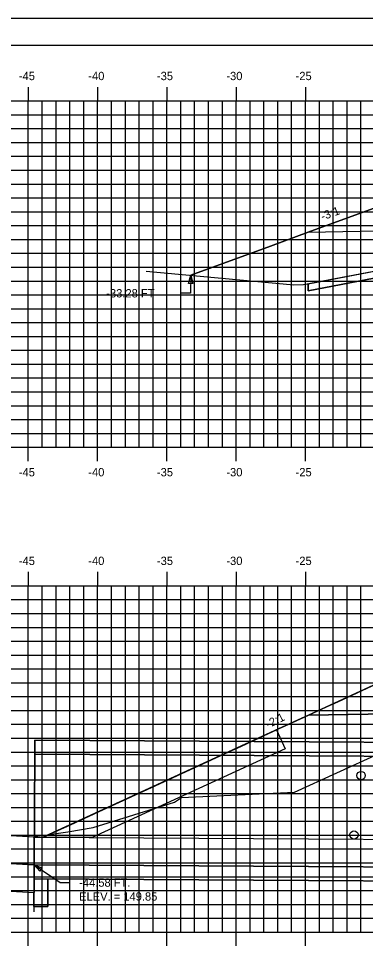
# Model space of a CAD drawing. Extents: x 1141202 to 1141372, y 608981 to 609091.
# Drawn here: x 1141239.8 to 1141264.8, y 609024.1 to 609091.3 of the extents above; entities that cross this region are included whole.
import ezdxf

# ---------------------------------------------------------------- set-up
doc = ezdxf.new("R2010")
doc.units = 0
for name, color, linetype in [('ANNOTATION', 7, 'Continuous'), ('BORDER', 7, 'Continuous'), ('D_Drainage_Culvert', 7, 'Continuous'), ('D_Roadway_SlopeLines', 7, 'Continuous'), ('D_Roadway_SubGrade', 7, 'Continuous'), ('D_Text_Standard', 7, 'Continuous'), ('H_V ANNOTATION', 7, 'Continuous'), ('JUNK', 7, 'Continuous'), ('MAJOR', 7, 'Continuous'), ('MINOR', 7, 'Continuous'), ('PATTERNING', 7, 'Continuous'), ('PLOT BOUNDARY', 7, 'Continuous'), ('S_Drainage_Invert', 7, 'Continuous'), ('S_Roadway_Centerline', 7, 'Continuous'), ('SHADING', 7, 'Continuous')]:
    doc.layers.add(name, color=color, linetype=linetype)

msp = doc.modelspace()

# ---------------------------------------------------------------- linework, layer by layer
for points in [[(1141252.234, 609072.746), (1141257.978, 609074.853), (1141260.705, 609075.853), (1141267.513, 609078.349), (1141267.514, 609078.349), (1141274.514, 609078.629), (1141285.514, 609078.849), (1141296.514, 609078.629), (1141303.514, 609078.349), (1141309.224, 609075.875), (1141311.532, 609074.875), (1141326.721, 609068.292)], [(1141242.002, 609032.375), (1141243.124, 609032.891), (1141243.238, 609032.944), (1141245.256, 609033.872), (1141245.575, 609034.019), (1141247.445, 609034.879), (1141247.911, 609035.094), (1141249.603, 609035.873), (1141250.246, 609036.168), (1141251.729, 609036.851), (1141252.581, 609037.243), (1141252.713, 609037.304), (1141252.823, 609037.354), (1141253.764, 609037.788), (1141254.915, 609038.318), (1141255.575, 609038.621), (1141257.249, 609039.392), (1141257.489, 609039.502), (1141258.565, 609039.998), (1141259.055, 609040.223), (1141259.583, 609040.466), (1141260.728, 609040.994), (1141261.554, 609041.374), (1141261.916, 609041.54), (1141262.843, 609041.967), (1141264.248, 609042.614), (1141266.045, 609043.442)]]:
    msp.add_lwpolyline(points)
at = {"layer": 'BORDER'}
msp.add_lwpolyline([(1141210.514, 608984.335), (1141370.514, 608984.335), (1141370.514, 609089.335), (1141210.514, 609089.335)], close=True, dxfattribs=at)
at = {"layer": 'D_Drainage_Culvert'}
for points in [[(1141240.936, 609030.185), (1141240.985, 609038.185), (1141240.991, 609039.185), (1141335.989, 609038.605), (1141335.983, 609037.605), (1141335.934, 609029.606), (1141335.916, 609026.606), (1141334.916, 609026.612), (1141334.928, 609028.612), (1141335.928, 609028.606), (1141240.93, 609029.185), (1141240.918, 609027.185), (1141241.918, 609027.179), (1141241.93, 609029.179)], [(1141240.934, 609030.185), (1141335.934, 609029.606), (1141335.983, 609037.605), (1141240.985, 609038.185), (1141240.936, 609030.185)]]:
    msp.add_lwpolyline(points, dxfattribs=at)
at = {"layer": 'D_Roadway_SlopeLines'}
for p, q in [((1141260.705, 609072.14), (1141260.705, 609071.631)), ((1141260.721, 609040.991), (1141241.588, 609032.181))]:
    msp.add_line(p, q, dxfattribs=at)
for points in [[(1141260.705, 609075.853), (1141257.978, 609074.853)], [(1141257.978, 609074.853), (1141252.234, 609072.746)], [(1141260.705, 609071.631), (1141269.611, 609073.326), (1141272.09, 609073.949), (1141272.463, 609073.997), (1141275.785, 609074.489)], [(1141260.728, 609040.994), (1141258.565, 609039.998)], [(1141258.565, 609039.998), (1141242.002, 609032.375)]]:
    msp.add_lwpolyline(points, dxfattribs=at)
msp.add_lwpolyline([(1141273.617, 609041.209), (1141260.721, 609040.991), (1141266.047, 609043.443), (1141266.047, 609043.193), (1141273.617, 609043.459)], close=True, dxfattribs=at)
at = {"layer": 'D_Roadway_SubGrade'}
for points in [[(1141274.514, 609078.212), (1141274.514, 609078.379), (1141267.514, 609078.099), (1141267.514, 609078.349), (1141267.513, 609078.349), (1141260.705, 609075.853), (1141274.514, 609076.129)], [(1141273.617, 609043.291), (1141273.617, 609043.458), (1141266.046, 609043.192), (1141266.046, 609043.442), (1141266.045, 609043.442), (1141260.728, 609040.994), (1141273.617, 609041.208)]]:
    msp.add_lwpolyline(points, close=True, dxfattribs=at)
at = {"layer": 'D_Text_Standard'}
for points in [[(1141252.234, 609072.746), (1141252.22, 609071.45), (1141251.54, 609071.45)], [(1141240.934, 609030.185), (1141242.82, 609028.91), (1141243.5, 609028.91)]]:
    msp.add_lwpolyline(points, dxfattribs=at)
for points in [[(1141252.234, 609072.746), (1141252.373, 609072.163), (1141252.082, 609072.166)], [(1141240.934, 609030.185), (1141241.498, 609029.98), (1141241.335, 609029.739)]]:
    msp.add_lwpolyline(points, close=True, dxfattribs=at)
at = {"layer": 'JUNK'}
msp.add_lwpolyline([(1141240.97, 609036.102), (1141240.934, 609030.185), (1141240.913, 609026.794)], dxfattribs=at)
at = {"layer": 'MAJOR'}
for p, q in [((1141240.514, 609086.337), (1141240.514, 609085.335)), ((1141245.514, 609086.337), (1141245.514, 609085.335)), ((1141250.514, 609086.337), (1141250.514, 609085.335)), ((1141255.514, 609086.337), (1141255.514, 609085.335)), ((1141260.514, 609086.337), (1141260.514, 609085.335)), ((1141215.514, 609085.335), (1141355.514, 609085.335)), ((1141215.514, 609085.335), (1141355.514, 609085.335)), ((1141240.514, 609060.335), (1141240.514, 609085.335)), ((1141245.514, 609060.335), (1141245.514, 609085.335)), ((1141250.514, 609060.335), (1141250.514, 609085.335)), ((1141255.514, 609060.335), (1141255.514, 609085.335)), ((1141260.514, 609060.335), (1141260.514, 609085.335)), ((1141215.514, 609080.335), (1141355.514, 609080.335)), ((1141215.514, 609075.335), (1141355.514, 609075.335)), ((1141215.514, 609070.335), (1141355.514, 609070.335)), ((1141215.514, 609065.335), (1141355.514, 609065.335)), ((1141215.514, 609060.335), (1141355.514, 609060.335)), ((1141215.514, 609060.335), (1141355.514, 609060.335)), ((1141240.514, 609059.333), (1141240.514, 609060.335)), ((1141245.514, 609059.333), (1141245.514, 609060.335)), ((1141250.514, 609059.333), (1141250.514, 609060.335)), ((1141255.514, 609059.333), (1141255.514, 609060.335)), ((1141260.514, 609059.333), (1141260.514, 609060.335)), ((1141240.514, 609051.337), (1141240.514, 609050.335)), ((1141245.514, 609051.337), (1141245.514, 609050.335)), ((1141250.514, 609051.337), (1141250.514, 609050.335)), ((1141255.514, 609051.337), (1141255.514, 609050.335)), ((1141260.514, 609051.337), (1141260.514, 609050.335)), ((1141215.514, 609050.335), (1141355.514, 609050.335)), ((1141215.514, 609050.335), (1141355.514, 609050.335)), ((1141240.514, 609025.335), (1141240.514, 609050.335)), ((1141245.514, 609025.335), (1141245.514, 609050.335)), ((1141250.514, 609025.335), (1141250.514, 609050.335)), ((1141255.514, 609025.335), (1141255.514, 609050.335)), ((1141260.514, 609025.335), (1141260.514, 609050.335)), ((1141215.514, 609045.335), (1141355.514, 609045.335)), ((1141215.514, 609040.335), (1141355.514, 609040.335)), ((1141215.514, 609035.335), (1141355.514, 609035.335)), ((1141215.514, 609030.335), (1141355.514, 609030.335)), ((1141215.514, 609025.335), (1141355.514, 609025.335)), ((1141215.514, 609025.335), (1141355.514, 609025.335)), ((1141240.514, 609024.333), (1141240.514, 609025.335)), ((1141245.514, 609024.333), (1141245.514, 609025.335)), ((1141250.514, 609024.333), (1141250.514, 609025.335)), ((1141255.514, 609024.333), (1141255.514, 609025.335)), ((1141260.514, 609024.333), (1141260.514, 609025.335))]:
    msp.add_line(p, q, dxfattribs=at)
at = {"layer": 'MINOR'}
for p, q in [((1141241.514, 609060.335), (1141241.514, 609085.335)), ((1141242.514, 609060.335), (1141242.514, 609085.335)), ((1141243.514, 609060.335), (1141243.514, 609085.335)), ((1141244.514, 609060.335), (1141244.514, 609085.335)), ((1141246.514, 609060.335), (1141246.514, 609085.335)), ((1141247.514, 609060.335), (1141247.514, 609085.335)), ((1141248.514, 609060.335), (1141248.514, 609085.335)), ((1141249.514, 609060.335), (1141249.514, 609085.335)), ((1141251.514, 609060.335), (1141251.514, 609085.335)), ((1141252.514, 609060.335), (1141252.514, 609085.335)), ((1141253.514, 609060.335), (1141253.514, 609085.335)), ((1141254.514, 609060.335), (1141254.514, 609085.335)), ((1141256.514, 609060.335), (1141256.514, 609085.335)), ((1141257.514, 609060.335), (1141257.514, 609085.335)), ((1141258.514, 609060.335), (1141258.514, 609085.335)), ((1141259.514, 609060.335), (1141259.514, 609085.335)), ((1141261.514, 609060.335), (1141261.514, 609085.335)), ((1141262.514, 609060.335), (1141262.514, 609085.335)), ((1141263.514, 609060.335), (1141263.514, 609085.335)), ((1141264.514, 609060.335), (1141264.514, 609085.335)), ((1141215.514, 609084.335), (1141355.514, 609084.335)), ((1141215.514, 609083.335), (1141355.514, 609083.335)), ((1141215.514, 609082.335), (1141355.514, 609082.335)), ((1141215.514, 609081.335), (1141355.514, 609081.335)), ((1141215.514, 609079.335), (1141355.514, 609079.335)), ((1141215.514, 609078.335), (1141355.514, 609078.335)), ((1141215.514, 609077.335), (1141355.514, 609077.335)), ((1141215.514, 609076.335), (1141355.514, 609076.335)), ((1141215.514, 609074.335), (1141355.514, 609074.335)), ((1141215.514, 609073.335), (1141355.514, 609073.335)), ((1141215.514, 609072.335), (1141355.514, 609072.335)), ((1141215.514, 609071.335), (1141355.514, 609071.335)), ((1141215.514, 609069.335), (1141355.514, 609069.335)), ((1141215.514, 609068.335), (1141355.514, 609068.335)), ((1141215.514, 609067.335), (1141355.514, 609067.335)), ((1141215.514, 609066.335), (1141355.514, 609066.335)), ((1141215.514, 609064.335), (1141355.514, 609064.335)), ((1141215.514, 609063.335), (1141355.514, 609063.335)), ((1141215.514, 609062.335), (1141355.514, 609062.335)), ((1141215.514, 609061.335), (1141355.514, 609061.335)), ((1141241.514, 609025.335), (1141241.514, 609050.335)), ((1141242.514, 609025.335), (1141242.514, 609050.335)), ((1141243.514, 609025.335), (1141243.514, 609050.335)), ((1141244.514, 609025.335), (1141244.514, 609050.335)), ((1141246.514, 609025.335), (1141246.514, 609050.335)), ((1141247.514, 609025.335), (1141247.514, 609050.335)), ((1141248.514, 609025.335), (1141248.514, 609050.335)), ((1141249.514, 609025.335), (1141249.514, 609050.335)), ((1141251.514, 609025.335), (1141251.514, 609050.335)), ((1141252.514, 609025.335), (1141252.514, 609050.335)), ((1141253.514, 609025.335), (1141253.514, 609050.335)), ((1141254.514, 609025.335), (1141254.514, 609050.335)), ((1141256.514, 609025.335), (1141256.514, 609050.335)), ((1141257.514, 609025.335), (1141257.514, 609050.335)), ((1141258.514, 609025.335), (1141258.514, 609050.335)), ((1141259.514, 609025.335), (1141259.514, 609050.335)), ((1141261.514, 609025.335), (1141261.514, 609050.335)), ((1141262.514, 609025.335), (1141262.514, 609050.335)), ((1141263.514, 609025.335), (1141263.514, 609050.335)), ((1141264.514, 609025.335), (1141264.514, 609050.335)), ((1141215.514, 609049.335), (1141355.514, 609049.335)), ((1141215.514, 609048.335), (1141355.514, 609048.335)), ((1141215.514, 609047.335), (1141355.514, 609047.335)), ((1141215.514, 609046.335), (1141355.514, 609046.335)), ((1141215.514, 609044.335), (1141355.514, 609044.335)), ((1141215.514, 609043.335), (1141355.514, 609043.335)), ((1141215.514, 609042.335), (1141355.514, 609042.335)), ((1141215.514, 609041.335), (1141355.514, 609041.335)), ((1141215.514, 609039.335), (1141355.514, 609039.335)), ((1141215.514, 609038.335), (1141355.514, 609038.335)), ((1141215.514, 609037.335), (1141355.514, 609037.335)), ((1141215.514, 609036.335), (1141355.514, 609036.335)), ((1141215.514, 609034.335), (1141355.514, 609034.335)), ((1141215.514, 609033.335), (1141355.514, 609033.335)), ((1141215.514, 609032.335), (1141355.514, 609032.335)), ((1141215.514, 609031.335), (1141355.514, 609031.335)), ((1141215.514, 609029.335), (1141355.514, 609029.335)), ((1141215.514, 609028.335), (1141355.514, 609028.335)), ((1141215.514, 609027.335), (1141355.514, 609027.335)), ((1141215.514, 609026.335), (1141355.514, 609026.335))]:
    msp.add_line(p, q, dxfattribs=at)
at = {"layer": 'PATTERNING'}
for points in [[(1141241.588, 609032.181), (1141249.983, 609036.047), (1141258.409, 609039.926), (1141259.037, 609038.563), (1141245.124, 609032.16)], [(1141240.991, 609039.185), (1141240.985, 609038.185), (1141335.983, 609037.605), (1141335.989, 609038.605)], [(1141240.946, 609032.185), (1141231.144, 609032.751), (1141231.144, 609030.751), (1141240.934, 609030.186)], [(1141335.946, 609031.606), (1141335.934, 609029.606), (1141240.934, 609030.185), (1141240.946, 609032.185)], [(1141240.946, 609030.185), (1141231.144, 609030.751), (1141231.144, 609028.751), (1141240.934, 609028.186)], [(1141335.928, 609028.606), (1141335.934, 609029.606), (1141240.934, 609030.185), (1141240.93, 609029.185)], [(1141240.93, 609029.185), (1141241.93, 609029.179), (1141241.918, 609027.179), (1141240.918, 609027.185)]]:
    msp.add_lwpolyline(points, close=True, dxfattribs=at)
at = {"layer": 'PLOT BOUNDARY'}
msp.add_lwpolyline([(1141202.421, 608981.276), (1141372.421, 608981.276), (1141372.421, 609091.276), (1141202.421, 609091.276)], close=True, dxfattribs=at)
at = {"layer": 'S_Drainage_Invert'}
for centre in [(1141264.523, 609036.636), (1141264.011, 609032.349)]:
    msp.add_circle(centre, 0.3, dxfattribs=at)
at = {"layer": 'S_Roadway_Centerline'}
for points in [[(1141249.019, 609073.048), (1141259.669, 609072.048), (1141260.38, 609072.078), (1141269.503, 609073.815), (1141271.998, 609074.442), (1141272.395, 609074.492), (1141275.785, 609074.994), (1141277.244, 609075.043), (1141286.655, 609075.349), (1141288.005, 609075.271), (1141297.528, 609074.852), (1141298.041, 609074.742), (1141301.372, 609074.078), (1141302.571, 609073.566), (1141306.003, 609072.179), (1141313.651, 609070.289), (1141315, 609070.011)], [(1141238.303, 609032.434), (1141240.853, 609032.205), (1141243.375, 609032.577), (1141245.2, 609032.879), (1141251.055, 609034.71), (1141251.563, 609035.05), (1141259.713, 609035.449), (1141265.819, 609038.239), (1141271.628, 609039.59), (1141274.411, 609039.914), (1141275.053, 609040.002), (1141284.311, 609040.287), (1141286.912, 609040.365), (1141295.122, 609039.926), (1141298.757, 609039.782), (1141301.617, 609039.219), (1141303.144, 609038.939), (1141307.342, 609037.277), (1141307.866, 609036.952), (1141309.238, 609036.47), (1141312.023, 609035.648), (1141315.938, 609034.498)]]:
    msp.add_lwpolyline(points, dxfattribs=at)
at = {"layer": 'SHADING'}
msp.add_lwpolyline([(1141275.785, 609074.994), (1141275.785, 609074.494), (1141272.09, 609073.949), (1141269.611, 609073.326), (1141260.705, 609071.631), (1141260.705, 609072.14), (1141269.503, 609073.815), (1141271.998, 609074.442)], close=True, dxfattribs=at)

# ---------------------------------------------------------------- texts
at = {"layer": 'ANNOTATION'}
for s, rotation, p in [('-3:1', 20.13617, (1141261.742, 609076.698)), ('-2:1', 26.56505, (1141257.836, 609040.038))]:
    msp.add_text(s, height=0.6, rotation=rotation, dxfattribs=at).set_placement(p)
at = {"layer": 'D_Text_Standard'}
for s, p in [('-33.28 FT', (1141246.139, 609071.15)), ('-44.58 FT.', (1141244.18, 609028.61)), ('ELEV. = 149.85', (1141244.18, 609027.61))]:
    msp.add_text(s, height=0.6, dxfattribs=at).set_placement(p)
at = {"layer": 'H_V ANNOTATION'}
for s, p in [('-45', (1141239.832, 609086.835)), ('-40', (1141244.84, 609086.835)), ('-35', (1141249.794, 609086.835)), ('-30', (1141254.802, 609086.835)), ('-25', (1141259.8, 609086.835)), ('-45', (1141239.832, 609058.235)), ('-40', (1141244.84, 609058.235)), ('-35', (1141249.794, 609058.235)), ('-30', (1141254.802, 609058.235)), ('-25', (1141259.8, 609058.235)), ('-45', (1141239.832, 609051.835)), ('-40', (1141244.84, 609051.835)), ('-35', (1141249.794, 609051.835)), ('-30', (1141254.802, 609051.835)), ('-25', (1141259.8, 609051.835))]:
    msp.add_text(s, height=0.6, dxfattribs=at).set_placement(p)

doc.saveas('drawing.dxf')
